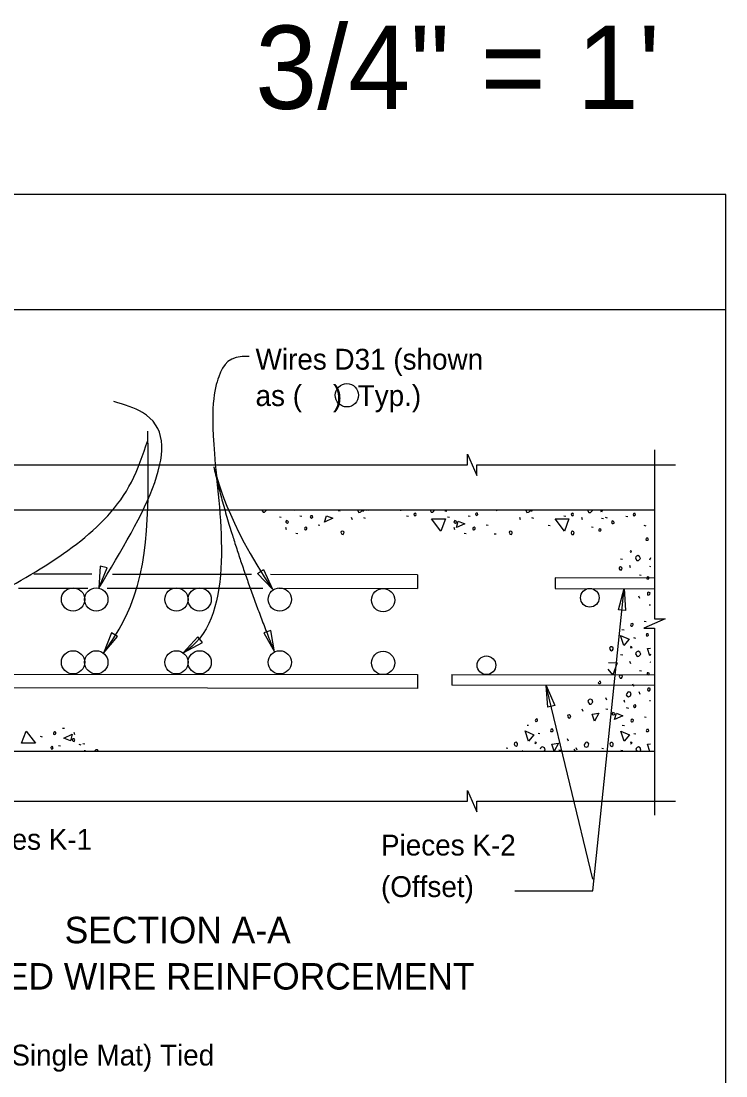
# Model space of a CAD drawing. Extents: x 4.6 to 40.7, y -0.4 to 17.4.
# Drawn here: x 21.76 to 25.17, y 12.32 to 17.42 of the extents above; entities that cross this region are included whole.
import ezdxf

# ---------------------------------------------------------------- set-up
doc = ezdxf.new("R2010")
doc.units = 0
for name, color, linetype in [('ActivePts-ConstElements', 7, 'Continuous'), ('BeamConc', 7, 'Continuous'), ('Dimension', 7, 'Continuous'), ('Miscellaneous', 7, 'Continuous'), ('Rebar', 7, 'Continuous'), ('Rebar_h', 7, 'Continuous'), ('TextStructures', 7, 'Continuous')]:
    doc.layers.add(name, color=color, linetype=linetype)

msp = doc.modelspace()

# ---------------------------------------------------------------- linework, layer by layer
at = {"layer": 'ActivePts-ConstElements'}
msp.add_lwpolyline([(4.6388, 3.607), (25.1721, 3.607), (25.1721, 16.5801), (4.6388, 16.5801)], close=True, dxfattribs=at)
at = {"layer": 'BeamConc'}
for p, q in [((24.827, 15.0519), (20.6792, 15.0519)), ((24.827, 13.8852), (20.6792, 13.8852))]:
    msp.add_line(p, q, dxfattribs=at)
at = {"layer": 'Dimension'}
for p, q in [((4.6388, 16.0235), (25.1722, 16.0235)), ((24.5281, 13.2676), (24.3062, 14.1891))]:
    msp.add_line(p, q, dxfattribs=at)
for points in [[(20.5818, 15.2718), (21.6377, 15.2718), (21.6377, 15.3235), (21.6602, 15.2718), (21.6827, 15.2202), (21.6827, 15.2718), (22.5724, 15.2718)], [(22.5101, 15.2718), (23.922, 15.2718), (23.922, 15.3235), (23.9445, 15.2718), (23.967, 15.2202), (23.967, 15.2718), (24.9291, 15.2718)], [(24.827, 15.345), (24.827, 14.5269), (24.8787, 14.5269), (24.827, 14.5044), (24.7753, 14.4819), (24.827, 14.4819), (24.827, 13.5774)], [(24.1507, 13.2114), (24.5281, 13.2114), (24.6804, 14.6729)], [(20.569, 13.6447), (21.6377, 13.6447), (21.6377, 13.6963), (21.6602, 13.6447), (21.6827, 13.593), (21.6827, 13.6447), (22.5724, 13.6447)], [(22.5724, 13.6447), (23.922, 13.6447), (23.922, 13.6963), (23.9445, 13.6447), (23.967, 13.593), (23.967, 13.6447), (24.9291, 13.6447)]]:
    msp.add_lwpolyline(points, dxfattribs=at)
for points in [[(22.1385, 14.6755), (22.1794, 14.7729), (22.145, 14.7809)], [(22.9349, 14.7657), (22.979, 14.6698), (22.9058, 14.7458)], [(24.652, 14.5711), (24.6804, 14.6729), (24.6871, 14.5675)], [(22.1603, 14.3611), (22.2293, 14.441), (22.1991, 14.4593)], [(22.5463, 14.3622), (22.6396, 14.4118), (22.6181, 14.4397)], [(22.988, 14.3669), (22.9705, 14.4711), (22.9372, 14.4595)], [(24.3099, 14.0995), (24.3026, 14.2049), (24.3442, 14.1078)]]:
    msp.add_lwpolyline(points, close=True, dxfattribs=at)
for points, degree in [([(22.8651, 15.7964), (22.7657, 15.7992), (22.7172, 15.7181), (22.655, 15.4727), (22.8004, 14.5148), (22.5463, 14.3622)], 3), ([(22.6942, 15.2619), (22.7798, 14.8859), (22.988, 14.3669)], 2), ([(22.6945, 15.2603), (22.71, 15.2163), (22.7536, 15.0002), (22.979, 14.6698)], 3)]:
    msp.add_open_spline(points, degree=degree, dxfattribs=at)
at = {"layer": 'Miscellaneous'}
for p, q in [((23.0842, 15.0505), (23.0837, 15.0519)), ((23.6001, 15.0493), (23.5992, 15.0519)), ((24.0632, 15.0481), (24.0618, 15.0519)), ((23.0117, 15.0204), (23.0211, 15.0181)), ((23.1112, 15.0258), (23.1212, 15.024)), ((23.2957, 15.0511), (23.3057, 15.0493)), ((23.3652, 15.0063), (23.3611, 15.0175)), ((23.4181, 15.0163), (23.4275, 15.014)), ((23.6272, 15.0246), (23.6372, 15.0228)), ((23.8116, 15.0499), (23.8216, 15.0482)), ((23.8257, 15.0204), (23.8351, 15.0181)), ((23.9252, 15.0258), (23.9352, 15.024)), ((24.1792, 15.0063), (24.1751, 15.0175)), ((24.2321, 15.0163), (24.2415, 15.014)), ((24.3883, 15.0246), (24.3983, 15.0228)), ((24.4789, 15.0052), (24.4747, 15.0163)), ((24.5702, 15.014), (24.5796, 15.0116)), ((24.5884, 15.0181), (24.5979, 15.0157)), ((24.688, 15.0234), (24.698, 15.0217)), ((23.047, 14.958), (23.0429, 14.9692)), ((23.199, 14.9816), (23.2079, 14.9798)), ((23.861, 14.958), (23.8569, 14.9692)), ((24.013, 14.9816), (24.0219, 14.9798)), ((24.3127, 14.9804), (24.3215, 14.9786)), ((24.5213, 14.9722), (24.5301, 14.9704)), ((24.7758, 14.9792), (24.7846, 14.9775)), ((23.0912, 14.9409), (23.1018, 14.9397)), ((23.9052, 14.9409), (23.9158, 14.9397)), ((24.0502, 14.9386), (24.0608, 14.9374)), ((24.6615, 14.8178), (24.6715, 14.816)), ((24.711, 14.773), (24.7069, 14.7842)), ((24.8023, 14.7819), (24.8074, 14.7806)), ((24.7534, 14.74), (24.7623, 14.7383)), ((24.7557, 14.6246), (24.751, 14.6364)), ((24.8017, 14.5951), (24.8074, 14.5943)), ((24.777, 14.5161), (24.7858, 14.5144)), ((24.6691, 14.4755), (24.6797, 14.4743)), ((24.7251, 14.436), (24.7345, 14.4336)), ((24.6627, 14.3547), (24.6727, 14.353)), ((24.7122, 14.3099), (24.7081, 14.3211)), ((24.8035, 14.3188), (24.8074, 14.3178)), ((24.7546, 14.2769), (24.7634, 14.2752)), ((24.7269, 14.1997), (24.7222, 14.2115)), ((24.5966, 14.1337), (24.5919, 14.1455)), ((24.7569, 14.1615), (24.7522, 14.1733)), ((24.4812, 14.079), (24.4771, 14.0902)), ((24.5908, 14.0919), (24.6002, 14.0896)), ((24.6833, 14.122), (24.6792, 14.1332)), ((24.6903, 14.0973), (24.7004, 14.0955)), ((24.8029, 14.132), (24.8074, 14.1314)), ((24.7781, 14.0531), (24.787, 14.0513)), ((21.973, 13.9959), (21.9624, 13.997)), ((24.2114, 14.0131), (24.2178, 14.0124)), ((24.6703, 14.0124), (24.6809, 14.0112)), ((21.8651, 13.9552), (21.8563, 13.957)), ((22.0171, 13.9787), (22.0212, 13.9675)), ((24.2632, 13.9741), (24.2726, 13.9717)), ((24.4105, 13.9352), (24.4058, 13.947)), ((24.7263, 13.9729), (24.7357, 13.9706)), ((21.9529, 13.911), (21.9429, 13.9128)), ((21.96, 13.8863), (21.9605, 13.8849)), ((22.0525, 13.9163), (22.043, 13.9187)), ((22.0707, 13.9204), (22.0613, 13.9228)), ((24.1089, 13.9022), (24.1171, 13.9011)), ((24.3642, 13.8928), (24.3742, 13.8911)), ((24.4524, 13.891), (24.4482, 13.9022)), ((24.5719, 13.9011), (24.5802, 13.8999)), ((24.6639, 13.8916), (24.6739, 13.8899))]:
    msp.add_line(p, q, dxfattribs=at)
for points in [[(22.9272, 15.0519), (22.9328, 15.0429), (22.9404, 15.0435), (22.9434, 15.0464), (22.9488, 15.0519)], [(23.3895, 15.0519), (23.3958, 15.0417), (23.4035, 15.0423), (23.4064, 15.0452), (23.4129, 15.0517), (23.4129, 15.0519)], [(23.418, 15.0458), (23.4161, 15.0519)], [(23.4212, 15.0519), (23.418, 15.0458)], [(23.4344, 15.051), (23.4341, 15.0519)], [(23.4402, 15.0519), (23.4389, 15.0494)], [(23.7412, 15.0519), (23.7468, 15.0429), (23.7544, 15.0435), (23.7574, 15.0464), (23.7628, 15.0519)], [(24.2035, 15.0519), (24.2098, 15.0417), (24.2175, 15.0423), (24.2204, 15.0452), (24.2269, 15.0517), (24.2269, 15.0519)], [(24.232, 15.0458), (24.2301, 15.0519)], [(24.2352, 15.0519), (24.232, 15.0458)], [(24.5025, 15.0519), (24.5095, 15.0405), (24.5172, 15.0411), (24.5201, 15.044), (24.5266, 15.0505), (24.526, 15.0519)], [(24.5702, 15.0434), (24.5674, 15.0519)], [(24.5745, 15.0519), (24.5702, 15.0434)], [(23.0459, 14.991), (23.05, 14.9904), (23.0541, 14.9922), (23.0553, 14.9957), (23.0535, 14.9986), (23.05, 15.001), (23.0459, 15.0028), (23.0435, 14.998), (23.0423, 14.9945), (23.0459, 14.991)], [(23.1635, 15.0162), (23.1671, 15.0126), (23.1706, 15.015), (23.173, 15.0185), (23.1718, 15.0244), (23.1688, 15.025), (23.1647, 15.0244), (23.1612, 15.0209), (23.1635, 15.0162)], [(23.2302, 14.9951), (23.2396, 15.0258), (23.2708, 15.0134), (23.2302, 14.9951)], [(23.6643, 15.0287), (23.6678, 15.0252), (23.6714, 15.0275), (23.6737, 15.0311), (23.6725, 15.037), (23.6696, 15.0376), (23.6655, 15.037), (23.6619, 15.0334), (23.6643, 15.0287)], [(23.7933, 14.9515), (23.7486, 15.0105), (23.8151, 15.0099), (23.7933, 14.9515)], [(23.8599, 14.991), (23.864, 14.9904), (23.8681, 14.9922), (23.8693, 14.9957), (23.8675, 14.9986), (23.864, 15.001), (23.8599, 15.0028), (23.8575, 14.998), (23.8563, 14.9945), (23.8599, 14.991)], [(23.9623, 15.0299), (23.9659, 15.0264), (23.9694, 15.0287), (23.9718, 15.0323), (23.9706, 15.0381), (23.9677, 15.0387), (23.9635, 15.0381), (23.96, 15.0346), (23.9623, 15.0299)], [(24.3911, 14.9515), (24.3463, 15.0105), (24.4129, 15.0099), (24.3911, 14.9515)], [(24.4254, 15.0287), (24.429, 15.0252), (24.4325, 15.0275), (24.4349, 15.0311), (24.4337, 15.037), (24.4307, 15.0376), (24.4266, 15.037), (24.4231, 15.0334), (24.4254, 15.0287)], [(24.7251, 15.0275), (24.7286, 15.024), (24.7322, 15.0264), (24.7345, 15.0299), (24.7334, 15.0358), (24.7304, 15.0364), (24.7263, 15.0358), (24.7227, 15.0323), (24.7251, 15.0275)], [(23.1366, 14.9568), (23.1389, 14.9568), (23.1436, 14.9592), (23.1454, 14.9645), (23.1448, 14.9674), (23.1401, 14.9698), (23.1342, 14.9663), (23.133, 14.9627), (23.1342, 14.9592), (23.1366, 14.9568)], [(23.3104, 14.9421), (23.3133, 14.9368), (23.3204, 14.9356), (23.3234, 14.9409), (23.3245, 14.9456), (23.3216, 14.9486), (23.3163, 14.9515), (23.311, 14.9498), (23.3092, 14.9445), (23.3104, 14.9421)], [(23.8681, 14.9686), (23.8775, 14.9993), (23.9087, 14.9869), (23.8681, 14.9686)], [(23.9506, 14.9568), (23.9529, 14.9568), (23.9576, 14.9592), (23.9594, 14.9645), (23.9588, 14.9674), (23.9541, 14.9698), (23.9482, 14.9663), (23.947, 14.9627), (23.9482, 14.9592), (23.9506, 14.9568)], [(24.1244, 14.9421), (24.1273, 14.9368), (24.1344, 14.9356), (24.1374, 14.9409), (24.1385, 14.9456), (24.1356, 14.9486), (24.1303, 14.9515), (24.125, 14.9498), (24.1232, 14.9445), (24.1244, 14.9421)], [(24.4241, 14.9409), (24.427, 14.9356), (24.4341, 14.9344), (24.437, 14.9397), (24.4382, 14.9445), (24.4353, 14.9474), (24.43, 14.9504), (24.4247, 14.9486), (24.4229, 14.9433), (24.4241, 14.9409)], [(24.5572, 14.9527), (24.5637, 14.9509), (24.5678, 14.9539), (24.5684, 14.958), (24.5673, 14.9592), (24.5625, 14.9615), (24.5584, 14.961), (24.5578, 14.9568), (24.5572, 14.9527)], [(24.6226, 14.9886), (24.6267, 14.988), (24.6309, 14.9898), (24.632, 14.9933), (24.6303, 14.9963), (24.6267, 14.9986), (24.6226, 15.0004), (24.6203, 14.9957), (24.6191, 14.9922), (24.6226, 14.9886)], [(24.7864, 14.9073), (24.7935, 14.9073), (24.797, 14.9109), (24.7952, 14.9174), (24.7876, 14.9179), (24.7864, 14.9144), (24.7846, 14.9115), (24.7864, 14.9073), (24.7852, 14.9085)], [(24.7104, 14.849), (24.7169, 14.852), (24.7145, 14.8543), (24.7104, 14.8561), (24.7086, 14.852), (24.7104, 14.849)], [(24.734, 14.8208), (24.7416, 14.8084), (24.7493, 14.809), (24.7522, 14.8119), (24.7587, 14.8184), (24.7546, 14.8284), (24.7464, 14.8331), (24.7405, 14.8308), (24.7357, 14.8261), (24.734, 14.8208)], [(24.8074, 14.8212), (24.8023, 14.8113)], [(24.6562, 14.769), (24.6591, 14.7636), (24.6662, 14.7625), (24.6692, 14.7678), (24.6703, 14.7725), (24.6674, 14.7754), (24.6621, 14.7784), (24.6568, 14.7766), (24.655, 14.7713), (24.6562, 14.769)], [(24.7894, 14.7206), (24.7959, 14.7188), (24.8, 14.7218), (24.8006, 14.7259), (24.7994, 14.7271), (24.7947, 14.7294), (24.7906, 14.7288), (24.79, 14.7247), (24.7894, 14.7206)], [(24.7923, 14.647), (24.7952, 14.6417), (24.8017, 14.6422), (24.8047, 14.6464), (24.8052, 14.6528), (24.8011, 14.6546), (24.7982, 14.6552), (24.7946, 14.654), (24.7935, 14.6528), (24.7923, 14.647)], [(24.7145, 14.4914), (24.7169, 14.4914), (24.7216, 14.4938), (24.7233, 14.4991), (24.7227, 14.502), (24.718, 14.5044), (24.7121, 14.5008), (24.711, 14.4973), (24.7121, 14.4938), (24.7145, 14.4914)], [(24.6786, 14.3977), (24.6627, 14.4466), (24.7045, 14.4284), (24.6786, 14.3977)], [(24.7876, 14.4443), (24.7946, 14.4443), (24.7982, 14.4478), (24.7964, 14.4543), (24.7887, 14.4549), (24.7876, 14.4513), (24.7858, 14.4484), (24.7876, 14.4443), (24.7864, 14.4454)], [(24.6096, 14.383), (24.6132, 14.3759), (24.6191, 14.3724), (24.6238, 14.3759), (24.6261, 14.3795), (24.6261, 14.3865), (24.6208, 14.3918), (24.6144, 14.3913), (24.6114, 14.3883), (24.6096, 14.383)], [(24.7116, 14.386), (24.7181, 14.3889), (24.7157, 14.3913), (24.7116, 14.393), (24.7098, 14.3889), (24.7116, 14.386)], [(24.7352, 14.3577), (24.7428, 14.3453), (24.7505, 14.3459), (24.7534, 14.3488), (24.7599, 14.3553), (24.7558, 14.3653), (24.7475, 14.37), (24.7416, 14.3677), (24.7369, 14.363), (24.7352, 14.3577)], [(24.8035, 14.3482), (24.7923, 14.383), (24.8074, 14.385)], [(24.8074, 14.3558), (24.8035, 14.3482)], [(24.6035, 14.315), (24.6462, 14.3147), (24.6244, 14.2563)], [(24.6244, 14.2563), (24.6033, 14.2841)], [(24.6574, 14.2457), (24.6603, 14.2404), (24.6674, 14.2392), (24.6703, 14.2445), (24.6715, 14.2492), (24.6686, 14.2522), (24.6633, 14.2551), (24.658, 14.2534), (24.6562, 14.2481), (24.6574, 14.2457)], [(24.7906, 14.2575), (24.797, 14.2557), (24.8012, 14.2587), (24.8017, 14.2628), (24.8006, 14.264), (24.7959, 14.2663), (24.7917, 14.2657), (24.7911, 14.2616), (24.7906, 14.2575)], [(24.5569, 14.2211), (24.5566, 14.2204), (24.5548, 14.2174), (24.5566, 14.2133), (24.5554, 14.2145)], [(24.5566, 14.2133), (24.5637, 14.2133), (24.5672, 14.2168), (24.5655, 14.2233), (24.559, 14.2238)], [(24.7935, 14.1839), (24.7964, 14.1786), (24.8029, 14.1792), (24.8058, 14.1833), (24.8064, 14.1898), (24.8023, 14.1915), (24.7994, 14.1921), (24.7958, 14.1909), (24.7946, 14.1898), (24.7935, 14.1839)], [(24.5042, 14.1267), (24.5119, 14.1143), (24.5195, 14.1149), (24.5225, 14.1179), (24.529, 14.1244), (24.5248, 14.1344), (24.5166, 14.1391), (24.5107, 14.1367), (24.506, 14.132), (24.5042, 14.1267)], [(24.6927, 14.1538), (24.7004, 14.1497), (24.7104, 14.1538), (24.7145, 14.1662), (24.7086, 14.1721), (24.701, 14.1738), (24.6974, 14.1715), (24.6933, 14.165), (24.6904, 14.1597), (24.6927, 14.1538)], [(24.7275, 14.1014), (24.731, 14.0978), (24.7345, 14.1002), (24.7369, 14.1037), (24.7357, 14.1096), (24.7328, 14.1102), (24.7286, 14.1096), (24.7251, 14.1061), (24.7275, 14.1014)], [(24.2526, 14.0295), (24.255, 14.0295), (24.2597, 14.0318), (24.2614, 14.0372), (24.2608, 14.0401), (24.2561, 14.0425), (24.2502, 14.0389), (24.2491, 14.0354), (24.2502, 14.0318), (24.2526, 14.0295)], [(24.4075, 14.0536), (24.4104, 14.0483), (24.4175, 14.0471), (24.4204, 14.0524), (24.4216, 14.0571), (24.4187, 14.0601), (24.4134, 14.063), (24.4081, 14.0613), (24.4063, 14.056), (24.4075, 14.0536)], [(24.5369, 14.0316), (24.5257, 14.0664), (24.5569, 14.0705), (24.5369, 14.0316)], [(24.625, 14.0625), (24.6291, 14.0619), (24.6332, 14.0636), (24.6344, 14.0672), (24.6326, 14.0701), (24.6291, 14.0725), (24.625, 14.0742), (24.6226, 14.0695), (24.6214, 14.066), (24.625, 14.0625)], [(24.6332, 14.0401), (24.6426, 14.0707), (24.6738, 14.0584), (24.6332, 14.0401)], [(24.7157, 14.0283), (24.718, 14.0283), (24.7227, 14.0307), (24.7245, 14.036), (24.7239, 14.0389), (24.7192, 14.0413), (24.7133, 14.0377), (24.7121, 14.0342), (24.7133, 14.0307), (24.7157, 14.0283)], [(21.7868, 13.9841), (21.8315, 13.9251), (21.765, 13.9257), (21.7868, 13.9841)], [(24.2167, 13.9358), (24.2008, 13.9847), (24.2426, 13.9665), (24.2167, 13.9358)], [(24.3257, 13.9824), (24.3327, 13.9824), (24.3363, 13.9859), (24.3345, 13.9924), (24.3268, 13.993), (24.3257, 13.9894), (24.3239, 13.9865), (24.3257, 13.9824), (24.3245, 13.9835)], [(24.6798, 13.9347), (24.6639, 13.9836), (24.7057, 13.9653), (24.6798, 13.9347)], [(24.7887, 13.9812), (24.7958, 13.9812), (24.7994, 13.9847), (24.7976, 13.9912), (24.7899, 13.9918), (24.7887, 13.9882), (24.787, 13.9853), (24.7887, 13.9812), (24.7876, 13.9824)], [(21.9276, 13.9799), (21.9252, 13.9799), (21.9205, 13.9776), (21.9187, 13.9723), (21.9193, 13.9693), (21.9241, 13.967), (21.9299, 13.9705), (21.9311, 13.974), (21.9299, 13.9776), (21.9276, 13.9799)], [(22.0101, 13.9682), (22.0007, 13.9375), (21.9694, 13.9499), (22.0101, 13.9682)], [(22.0183, 13.9458), (22.0142, 13.9464), (22.01, 13.9446), (22.0089, 13.9411), (22.0106, 13.9381), (22.0142, 13.9358), (22.0183, 13.934), (22.0207, 13.9387), (22.0218, 13.9423), (22.0183, 13.9458)], [(24.1477, 13.9211), (24.1513, 13.914), (24.1572, 13.9105), (24.1619, 13.914), (24.1642, 13.9176), (24.1642, 13.9246), (24.1589, 13.9299), (24.1525, 13.9294), (24.1495, 13.9264), (24.1477, 13.9211)], [(24.2497, 13.9241), (24.2562, 13.927), (24.2538, 13.9294), (24.2497, 13.9311), (24.2479, 13.927), (24.2497, 13.9241)], [(24.488, 13.91), (24.4957, 13.9059), (24.5057, 13.91), (24.5098, 13.9224), (24.5039, 13.9283), (24.4963, 13.93), (24.4927, 13.9277), (24.4886, 13.9212), (24.4857, 13.9159), (24.488, 13.91)], [(24.7128, 13.9229), (24.7193, 13.9258), (24.7169, 13.9282), (24.7128, 13.9299), (24.711, 13.9258), (24.7128, 13.9229)], [(21.9158, 13.9069), (21.9123, 13.9104), (21.9087, 13.9081), (21.9064, 13.9045), (21.9076, 13.8986), (21.9105, 13.898), (21.9146, 13.8986), (21.9182, 13.9022), (21.9158, 13.9069)], [(22.0676, 13.8849), (22.0707, 13.891)], [(22.0707, 13.891), (22.0727, 13.8849)], [(22.137, 13.8849), (22.1314, 13.8939), (22.1237, 13.8933), (22.1208, 13.8904), (22.1153, 13.8849)], [(24.1896, 13.8905), (24.1869, 13.8852)], [(24.2909, 13.8863), (24.2915, 13.8869), (24.298, 13.8934), (24.2939, 13.9034), (24.2856, 13.9081), (24.2797, 13.9058), (24.275, 13.9011), (24.2733, 13.8958)], [(24.3416, 13.8863), (24.3304, 13.9211), (24.3616, 13.9252), (24.3416, 13.8863)], [(24.4367, 13.8958), (24.4425, 13.8863)], [(24.6108, 13.9199), (24.6144, 13.9129), (24.6203, 13.9093), (24.625, 13.9129), (24.6273, 13.9164), (24.6273, 13.9235), (24.622, 13.9288), (24.6155, 13.9282), (24.6126, 13.9252), (24.6108, 13.9199)], [(24.7542, 13.8853), (24.7546, 13.8857), (24.7611, 13.8922), (24.757, 13.9022), (24.7487, 13.907), (24.7428, 13.9046), (24.7381, 13.8999), (24.7363, 13.8946)], [(24.7363, 13.8946), (24.7421, 13.8854)], [(24.8046, 13.8852), (24.7935, 13.9199), (24.8074, 13.9217)]]:
    msp.add_lwpolyline(points, dxfattribs=at)
at = {"layer": 'Rebar'}
for centre, radius in [((23.3384, 15.6082), 0.0563), ((22.0136, 14.6206), 0.0563), ((22.0136, 14.6206), 0.0563), ((22.1261, 14.6206), 0.0563), ((22.5137, 14.6206), 0.0563), ((22.5137, 14.6206), 0.0563), ((22.6262, 14.6206), 0.0563), ((23.0136, 14.6206), 0.0563), ((23.5136, 14.6176), 0.0563), ((24.5136, 14.6288), 0.045), ((22.0136, 14.3165), 0.0563), ((22.1261, 14.3165), 0.0563), ((22.5137, 14.3165), 0.0563), ((22.6262, 14.3165), 0.0563), ((23.0136, 14.3165), 0.0563), ((23.0136, 14.3165), 0.0563), ((23.5136, 14.3134), 0.0563), ((24.0136, 14.3022), 0.045)]:
    msp.add_circle(centre, radius, dxfattribs=at)
at = {"layer": 'Rebar_h'}
for p, q in [((23.6803, 14.7405), (23.6803, 14.6739)), ((24.3469, 14.7249), (24.3469, 14.6732)), ((21.7489, 14.6759), (22.0847, 14.6755)), ((22.1794, 14.6754), (22.9316, 14.6746)), ((23.0098, 14.6746), (23.6803, 14.6739)), ((24.3469, 14.6732), (24.8263, 14.6727)), ((20.8469, 14.2602), (23.6803, 14.2572)), ((23.6803, 14.2572), (23.6803, 14.1905)), ((23.8469, 14.257), (23.8469, 14.2053)), ((23.8469, 14.257), (24.8273, 14.256)), ((23.6803, 14.1905), (20.8469, 14.1935)), ((24.8273, 14.2043), (23.8469, 14.2053))]:
    msp.add_line(p, q, dxfattribs=at)
for points in [[(22.1045, 14.7422), (21.8241, 14.7425)], [(22.877, 14.7414), (22.204, 14.7421)], [(23.6803, 14.7405), (22.9686, 14.7413)], [(24.8264, 14.7244), (24.3469, 14.7249)]]:
    msp.add_lwpolyline(points, dxfattribs=at)
at = {"layer": 'TextStructures'}
for points in [[(22.1385, 14.6755), (22.3491, 15.5251), (22.2112, 15.5778)], [(22.1603, 14.3611), (22.247, 14.494), (22.3766, 15.3329), (22.3758, 15.4345)], [(21.6676, 14.6585), (22.296, 15.1884), (22.3749, 15.3888)]]:
    msp.add_spline(points, degree=3, dxfattribs=at)

# ---------------------------------------------------------------- texts
at = {"layer": 'Dimension'}
for s, height, p in [('Wires D31 (shown ', 0.1008, (22.8966, 15.7323)), ('as (    )  Typ.)', 0.1008, (22.8966, 15.5563)), ('Pieces K-1', 0.1008, (21.4542, 13.4098)), ('Pieces K-2 ', 0.1008, (23.5035, 13.382)), ('(Offset)', 0.1008, (23.5035, 13.1812)), ('SECTION A-A', 0.128, (21.973, 12.9576)), ('FOR WELDED WIRE REINFORCEMENT', 0.128, (20.7804, 12.7336))]:
    msp.add_text(s, height=height, dxfattribs=at).set_placement(p)
msp.add_text('Pieces S (Single Mat) Tied ', height=0.1008, rotation=360, dxfattribs=at).set_placement((21.1008, 12.3661))
at = {"layer": 'TextStructures'}
msp.add_text('3/4" = 1\'', height=0.4032, dxfattribs=at).set_placement((22.8951, 16.9936))

doc.saveas('drawing.dxf')
